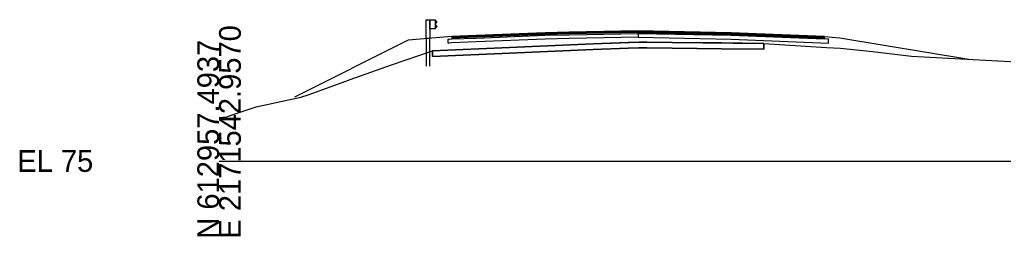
# Model space of a CAD drawing. Extents: x -26 to 1303, y -3010 to 12023.
# Drawn here: x -25.7 to 101, y 5490.3 to 5518.2 of the extents above; entities that cross this region are included whole.
import ezdxf

# ---------------------------------------------------------------- set-up
doc = ezdxf.new("R2010")
doc.units = 0
for name, color, linetype in [('RD_GPK_XS_Cell', 7, 'Continuous'), ('RD_PD_Final_TrvlWay', 7, 'Continuous'), ('RD_XS_Base', 7, 'Continuous'), ('RD_XS_ExGround', 7, 'Continuous'), ('RD_XS_ExPaveRet', 7, 'Continuous'), ('RD_XS_GR', 7, 'Continuous'), ('RD_XS_Greenside', 7, 'Continuous'), ('RD_XS_Pave', 7, 'Continuous'), ('RD_XS_PaveOvlay_CP', 7, 'Continuous'), ('RD_XS_TieSlope', 7, 'Continuous')]:
    doc.layers.add(name, color=color, linetype=linetype)

msp = doc.modelspace()

# ---------------------------------------------------------------- linework, layer by layer
at = {"layer": 'RD_GPK_XS_Cell'}
msp.add_line((0, 5500), (150, 5500), dxfattribs=at)
at = {"layer": 'RD_PD_Final_TrvlWay'}
msp.add_lwpolyline([(27.17, 5512.19), (27.17, 5515.8), (26.67, 5515.76), (26.67, 5512.19)], dxfattribs=at)
at = {"layer": 'RD_XS_Base'}
for p, q in [((30, 5515.71), (33.12, 5515.83)), ((33.12, 5515.83), (42, 5516.19)), ((42, 5516.19), (45.12, 5516.25)), ((45.12, 5515.75), (42, 5515.69)), ((45.12, 5516.25), (54, 5516.43)), ((54, 5515.93), (45.12, 5515.75)), ((54, 5516.47), (54, 5516.58)), ((54, 5516.58), (54, 5516.1)), ((54, 5516.43), (54, 5516.58)), ((54, 5516.58), (54, 5515.93)), ((54, 5516.43), (54, 5516.47)), ((54, 5516.43), (54, 5516.06)), ((54, 5516.43), (54, 5515.93)), ((66, 5516.19), (54, 5516.43)), ((54, 5516.43), (54, 5516.43)), ((54, 5516.1), (54, 5515.93)), ((54, 5516.06), (54, 5515.93)), ((54, 5515.93), (54, 5515.93)), ((54, 5515.93), (54, 5515.93)), ((54, 5515.93), (66, 5515.69)), ((78, 5515.71), (66, 5516.19)), ((68, 5516.11), (68, 5516.11)), ((29.5, 5515.32), (29.5, 5515.69)), ((29.5, 5515.69), (29.63, 5515.69)), ((29.5, 5515.19), (29.5, 5515.32)), ((29.63, 5515.19), (29.5, 5515.19)), ((29.63, 5515.69), (30, 5515.71)), ((30, 5515.21), (29.63, 5515.19)), ((33.12, 5515.33), (30, 5515.21)), ((42, 5515.69), (33.12, 5515.33)), ((66, 5515.69), (78.5, 5515.19)), ((68, 5515.61), (68, 5515.61)), ((78.5, 5515.69), (78, 5515.71)), ((78, 5515.71), (78, 5515.71)), ((78.5, 5515.19), (78.5, 5515.69)), ((78.5, 5515.69), (78.5, 5515.69)), ((78.5, 5515.19), (78.5, 5515.19)), ((78.5, 5515.19), (78.5, 5515.19))]:
    msp.add_line(p, q, dxfattribs=at)
at = {"layer": 'RD_XS_ExGround'}
msp.add_lwpolyline([(0, 5505.59), (0.99, 5505.68), (1.69, 5505.93), (4.77, 5506.99), (10.52, 5508.24), (11.49, 5508.5), (16.32, 5510.27), (16.9, 5510.5), (22.22, 5512.36), (27.5, 5514.19), (48.22, 5515.1), (54.09, 5515.32), (58.38, 5515.27), (70.21, 5515.13), (78.28, 5514.62), (80.05, 5514.52), (84.2, 5514.08), (89.21, 5513.49), (98.73, 5512.99), (105.14, 5512.65)], dxfattribs=at)
at = {"layer": 'RD_XS_ExPaveRet'}
for points in [[(64.75, 5515.2), (70.21, 5515.13), (70.21, 5514.79), (70.21, 5514.38), (64.75, 5514.45), (58.38, 5514.52), (55.12, 5514.56), (54.09, 5514.57), (52.69, 5514.52), (48.22, 5514.35), (37.43, 5513.88), (27.5, 5513.44), (27.5, 5513.44), (27.5, 5513.79), (27.5, 5514.19), (27.5, 5514.19), (37.43, 5514.63), (48.22, 5515.1), (52.69, 5515.27), (54.09, 5515.32), (55.12, 5515.31), (58.38, 5515.27), (64.75, 5515.2)], [(58.38, 5515.27), (55.12, 5515.31), (54.09, 5515.32), (52.69, 5515.27), (48.22, 5515.1), (37.43, 5514.63), (27.5, 5514.19), (27.5, 5513.79), (27.5, 5513.44), (37.43, 5513.88), (48.22, 5514.35), (52.69, 5514.52), (54.09, 5514.57), (55.12, 5514.56), (58.38, 5514.52), (64.75, 5514.45), (70.21, 5514.38), (70.21, 5514.79), (70.21, 5515.13), (64.75, 5515.2), (58.38, 5515.27)]]:
    msp.add_lwpolyline(points, dxfattribs=at)
at = {"layer": 'RD_XS_GR'}
for p, q in [((26.67, 5515.76), (26.67, 5518.19)), ((26.67, 5518.19), (26.92, 5518.19)), ((26.92, 5518.19), (27.17, 5518.19)), ((27.17, 5518.19), (27.17, 5515.8)), ((27.17, 5517.03), (27.17, 5518.19)), ((27.17, 5518.19), (27.83, 5518.19)), ((27.83, 5517.03), (27.17, 5517.03)), ((27.83, 5518.19), (27.83, 5517.03)), ((28.03, 5517.98), (27.83, 5518.19)), ((27.83, 5518.19), (27.83, 5517.33)), ((27.83, 5517.61), (27.9, 5517.68)), ((28.03, 5517.39), (27.83, 5517.61)), ((27.83, 5517.33), (27.83, 5517.03)), ((27.83, 5517.03), (27.9, 5517.1)), ((27.9, 5517.68), (28.1, 5517.9)), ((27.9, 5517.1), (28.1, 5517.32)), ((28.1, 5517.9), (28.03, 5517.98)), ((28.1, 5517.32), (28.03, 5517.39)), ((27.17, 5515.8), (26.67, 5515.76))]:
    msp.add_line(p, q, dxfattribs=at)
at = {"layer": 'RD_XS_Greenside'}
for p, q in [((80, 5515.86), (96.61, 5513.1)), ((24.35, 5515.57), (9.7, 5508.24))]:
    msp.add_line(p, q, dxfattribs=at)
at = {"layer": 'RD_XS_Pave'}
for p, q in [((33.12, 5516.15), (30, 5516.02)), ((30, 5516.02), (30, 5515.91)), ((33.12, 5515.99), (30, 5515.86)), ((30, 5515.86), (33.12, 5515.99)), ((30, 5515.91), (30, 5515.86)), ((30, 5515.86), (30, 5515.75)), ((30, 5515.71), (33.12, 5515.83)), ((30, 5515.75), (30, 5515.71)), ((42, 5516.5), (33.12, 5516.15)), ((42, 5516.34), (33.12, 5515.99)), ((33.12, 5515.99), (42, 5516.34)), ((33.12, 5515.83), (42, 5516.19)), ((45.12, 5516.57), (42, 5516.5)), ((45.12, 5516.41), (42, 5516.34)), ((42, 5516.34), (45.12, 5516.41)), ((42, 5516.19), (45.12, 5516.25)), ((54, 5516.74), (45.12, 5516.57)), ((54, 5516.58), (45.12, 5516.41)), ((45.12, 5516.41), (54, 5516.58)), ((45.12, 5516.25), (54, 5516.43)), ((66, 5516.5), (54, 5516.74)), ((54, 5516.47), (54, 5516.58)), ((54, 5516.58), (54, 5516.47)), ((54, 5516.43), (54, 5516.58)), ((54, 5516.58), (66, 5516.34)), ((66, 5516.34), (54, 5516.58)), ((54, 5516.58), (54, 5516.43)), ((54, 5516.43), (54, 5516.47)), ((54, 5516.47), (54, 5516.43)), ((54, 5516.43), (54, 5516.43)), ((54, 5516.43), (54, 5516.43)), ((54, 5516.43), (66, 5516.19)), ((78, 5516.02), (66, 5516.5)), ((66, 5516.34), (78, 5515.86)), ((78, 5515.86), (66, 5516.34)), ((66, 5516.19), (78, 5515.71)), ((68, 5516.42), (68, 5516.42)), ((68, 5516.26), (68, 5516.26)), ((68, 5516.26), (68, 5516.26)), ((68, 5516.11), (68, 5516.11)), ((78, 5515.86), (78, 5516.02)), ((78, 5516.02), (78, 5516.02)), ((78, 5515.86), (78, 5515.86)), ((78, 5515.86), (78, 5515.86)), ((78, 5515.71), (78, 5515.86)), ((78, 5515.86), (78, 5515.86)), ((78, 5515.71), (78, 5515.71)), ((78, 5515.71), (78, 5515.71))]:
    msp.add_line(p, q, dxfattribs=at)
at = {"layer": 'RD_XS_PaveOvlay_CP'}
for p, q in [((30, 5516.02), (42, 5516.5)), ((42, 5516.5), (54, 5516.74)), ((54, 5516.74), (66, 5516.5)), ((66, 5516.5), (78, 5516.02))]:
    msp.add_line(p, q, dxfattribs=at)
at = {"layer": 'RD_XS_TieSlope'}
for p, q in [((30, 5516.02), (24.35, 5515.57)), ((78, 5516.02), (80, 5515.86))]:
    msp.add_line(p, q, dxfattribs=at)

# ---------------------------------------------------------------- texts
at = {"layer": 'RD_GPK_XS_Cell'}
for s, p in [('E 2171542.9570', (2.8, 5490)), ('N 612957.4937', (0, 5490))]:
    msp.add_text(s, height=2.8, rotation=90, dxfattribs=at).set_placement(p)
msp.add_text('EL 75', height=2.8, dxfattribs=at).set_placement((-26, 5498.6))

doc.saveas('drawing.dxf')
